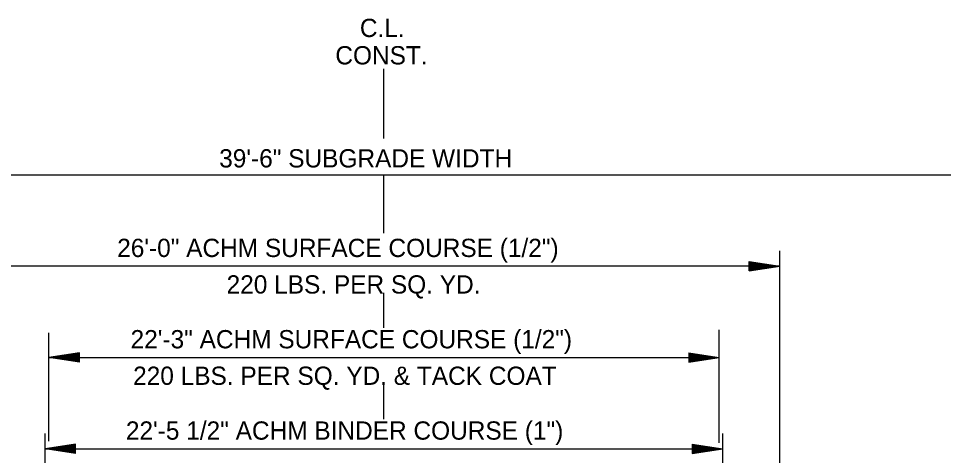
# Model space of a CAD drawing. Extents: x 2478 to 3210, y 439 to 841.
# Drawn here: x 2603 to 2663.8, y 508.7 to 537.4 of the extents above; entities that cross this region are included whole.
import ezdxf

# ---------------------------------------------------------------- set-up
doc = ezdxf.new("R2010")
doc.units = 0
for name, color, linetype in [('R_Annotation', 7, 'Continuous'), ('R_Centerline', 7, 'Continuous'), ('R_Dimension', 7, 'Continuous')]:
    doc.layers.add(name, color=color, linetype=linetype)

msp = doc.modelspace()

# ---------------------------------------------------------------- linework, layer by layer
at = {"layer": 'R_Centerline'}
for p, q in [((2627.034, 529.486), (2627.034, 534.048)), ((2627.034, 523.271), (2627.034, 527.094)), ((2627.034, 517.049), (2627.034, 519.333)), ((2627.034, 511.049), (2627.034, 513.333))]:
    msp.add_line(p, q, dxfattribs=at)
at = {"layer": 'R_Dimension'}
for p, q in [((2587.581, 527.094), (2666.487, 527.094)), ((2653.037, 503.594), (2653.037, 522.094)), ((2651.037, 521.394), (2653.037, 521.094)), ((2651.037, 520.794), (2651.037, 521.394)), ((2651.037, 521.344), (2652.703, 521.094)), ((2653.037, 521.094), (2601.03, 521.094)), ((2651.037, 521.293), (2652.359, 521.094)), ((2651.037, 521.243), (2652.026, 521.094)), ((2651.037, 521.192), (2651.687, 521.094)), ((2651.037, 521.141), (2651.353, 521.094)), ((2651.037, 520.794), (2653.037, 521.094)), ((2651.037, 520.997), (2651.687, 521.094)), ((2651.037, 520.895), (2652.359, 521.094)), ((2651.037, 520.844), (2652.703, 521.094)), ((2651.037, 520.945), (2652.026, 521.094)), ((2651.037, 521.047), (2651.353, 521.094)), ((2605.034, 509.601), (2605.034, 516.718)), ((2649.054, 509.496), (2649.054, 516.909)), ((2607.034, 515.395), (2605.034, 515.095)), ((2607.034, 515.345), (2605.368, 515.095)), ((2607.034, 515.294), (2605.712, 515.095)), ((2607.034, 515.244), (2606.045, 515.095)), ((2607.034, 514.795), (2607.034, 515.395)), ((2647.054, 515.394), (2649.054, 515.094)), ((2647.054, 515.394), (2647.054, 514.794)), ((2647.054, 515.344), (2648.72, 515.094)), ((2647.054, 515.293), (2648.376, 515.094)), ((2647.054, 515.243), (2648.043, 515.094)), ((2607.034, 514.795), (2605.034, 515.095)), ((2605.034, 515.094), (2649.055, 515.094)), ((2607.034, 514.845), (2605.368, 515.095)), ((2607.034, 514.896), (2605.712, 515.095)), ((2607.034, 514.946), (2606.045, 515.095)), ((2607.034, 515.193), (2606.384, 515.095)), ((2607.034, 514.998), (2606.384, 515.095)), ((2607.034, 515.142), (2606.718, 515.095)), ((2607.034, 515.048), (2606.718, 515.095)), ((2647.054, 515.191), (2647.704, 515.094)), ((2647.054, 515.141), (2647.37, 515.094)), ((2647.054, 514.794), (2649.054, 515.094)), ((2647.054, 514.996), (2647.704, 515.094)), ((2647.054, 514.895), (2648.376, 515.094)), ((2647.054, 514.844), (2648.72, 515.094)), ((2647.054, 514.945), (2648.043, 515.094)), ((2647.054, 515.047), (2647.37, 515.094)), ((2604.781, 503.594), (2604.781, 510.094)), ((2649.287, 503.594), (2649.287, 510.094)), ((2606.781, 509.394), (2604.781, 509.094)), ((2606.781, 509.344), (2605.115, 509.094)), ((2606.781, 509.293), (2605.459, 509.094)), ((2606.781, 509.243), (2605.792, 509.094)), ((2606.781, 509.192), (2606.131, 509.094)), ((2606.781, 508.794), (2606.781, 509.394)), ((2647.287, 509.394), (2649.287, 509.094)), ((2647.287, 509.394), (2647.287, 508.794)), ((2647.287, 509.344), (2648.953, 509.094)), ((2647.287, 509.293), (2648.609, 509.094)), ((2647.287, 509.243), (2648.276, 509.094)), ((2647.287, 509.191), (2647.937, 509.094)), ((2604.781, 509.094), (2649.287, 509.094)), ((2606.781, 508.794), (2604.781, 509.094)), ((2606.781, 508.844), (2605.115, 509.094)), ((2606.781, 508.895), (2605.459, 509.094)), ((2606.781, 508.945), (2605.792, 509.094)), ((2606.781, 508.997), (2606.131, 509.094)), ((2606.781, 509.141), (2606.465, 509.094)), ((2606.781, 509.047), (2606.465, 509.094)), ((2647.287, 509.141), (2647.603, 509.094)), ((2647.287, 508.794), (2649.287, 509.094)), ((2647.287, 508.996), (2647.937, 509.094)), ((2647.287, 508.895), (2648.609, 509.094)), ((2647.287, 508.844), (2648.953, 509.094)), ((2647.287, 508.945), (2648.276, 509.094)), ((2647.287, 509.047), (2647.603, 509.094))]:
    msp.add_line(p, q, dxfattribs=at)

# ---------------------------------------------------------------- texts
at = {"layer": 'R_Annotation'}
for s, p in [('C.L.', (2625.456, 536.148)), ('CONST.', (2623.845, 534.348)), ('39\'-6" SUBGRADE WIDTH', (2616.215, 527.579)), ('26\'-0" ACHM SURFACE COURSE (1/2")', (2609.514, 521.694)), ('220 LBS. PER SQ. YD.', (2616.702, 519.294)), ('22\'-3" ACHM SURFACE COURSE (1/2")', (2610.395, 515.694)), ('220 LBS. PER SQ. YD. & TACK COAT', (2610.56, 513.294)), ('22\'-5 1/2" ACHM BINDER COURSE (1")', (2610.086, 509.694))]:
    msp.add_text(s, height=1.2, dxfattribs=at).set_placement(p)

doc.saveas('drawing.dxf')
